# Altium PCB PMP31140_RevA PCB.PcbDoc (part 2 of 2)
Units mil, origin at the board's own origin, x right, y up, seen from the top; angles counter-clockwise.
Board outline 6181.25 x 1625 mil, 2 copper layers (Top Layer, Bottom Layer), stack 62 mil thick; 98 components, 49 nets, 210 pads, 6 vias.
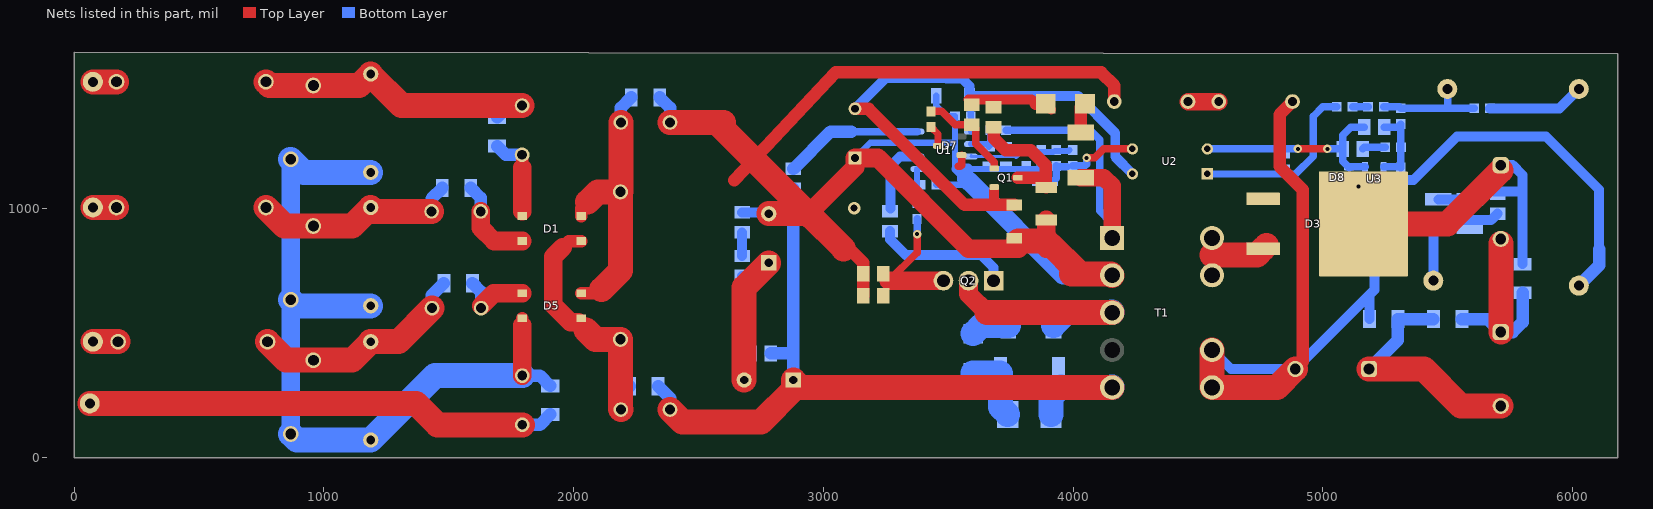
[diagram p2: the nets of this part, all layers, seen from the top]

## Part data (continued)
R34: library part CMP-0022325-3, "RES, 30.9 k, 1%, 0.1 W, 0603", Manufacturer=Vishay-Dale, Power_W=100mW, Supplier Part Number 1=541-30.9KHCT-ND, TempCo="100 ppm/C", Tolerance_%=1%, Value2=0.1W, Value_Code=30k9, ValueDisplayed=30.9k
R36: "RES, 100 k, 1%, 0.125 W, 0805", Manufacturer=Vishay-Dale, Power_W=0.125, Supplier Part Number 1=541-100KCCT-ND, TempCo="100 ppm/C", Tolerance_%=1, Value1=1%, Value2=0.125W, Value_Code=100k
R37: library part CRCW060322K1FKEA, "RES, 22.1 k, 1%, 0.1 W, 0603", Manufacturer=Vishay-Dale, Power_W=0.1, Supplier Part Number 1=541-22.1KHCT-ND, TempCo="100 ppm/C", Tolerance_%=1, Value1=1%, Value2=0.1W, Value_Code=22k1, ValueDisplayed=22.1k
RF1 RF2 RF3: library part CMP-0014490-1, "RES, 1.0, 5%, 1 W, TH, 2-Leads, Axial, Dia 3.8mm, Pin Spaing 15.2mm", Manufacturer="TT Electronics/IRC", Power_W=1W, Supplier Part Number 1=989-1255-1-ND, TempCo="300 ppm/C", Tolerance_%=5%, Value_Code=1R00, ValueDisplayed=1.0
RV1 RV2 RV3: library part CMP-0001853-2, "SIOV Metal Oxide Leaded Varistor, 300VAC, 3500A, TH", Manufacturer=TDK, Supplier Part Number 1=495-1434-ND
T1: library part CMP-0094613-1, "TRANSFORMER", Frequency_Fixed=65kHz, Manufacturer=Wurth, Operating Temperature Range="-40°C to +125°C", Voltage_Isolation_Vrms=4kV
TP1 TP2 TP4 TP6: library part CMP-0055137-1, "Test Point, Miniature, Red, TH", Color=Red, Manufacturer=Keystone, Supplier Part Number 1=36-5000-ND
TP3 TP7: "Test Point, Miniature, Red, TH", Color=Red, Manufacturer=Keystone, Supplier Part Number 1=36-5000-ND
TP5 TP8: "Test Point, Miniature, Black, TH", Color=Black, Manufacturer=Keystone, Supplier Part Number 1=36-5001-ND
U1: "Constant-Voltage, Constant-Current Flyback Controller Using Opto-Coupler Feedback, D0007A", Alternate Manufacturer="Texas Instruments", Alternate PartNumber=UCC28740D
U2: "Optocoupler, 5 kV, 80-160% CTR, TH", Manufacturer="Fairchild Semiconductor", Supplier Part Number 1=FOD817A-ND, Voltage_Isolation_Vrms=5000V
U3: library part CMP-0084731-1, "High Bandwidth Low-Iq Programmable Shunt Regulator, DBZ0003A (SOT-23-3)", Alternate Manufacturer="Texas Instruments"

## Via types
v1: diameter 34, hole 16, Top Layer to Bottom Layer, 5 vias
v2: diameter 50, hole 28, Top Layer to Bottom Layer, 1 vias

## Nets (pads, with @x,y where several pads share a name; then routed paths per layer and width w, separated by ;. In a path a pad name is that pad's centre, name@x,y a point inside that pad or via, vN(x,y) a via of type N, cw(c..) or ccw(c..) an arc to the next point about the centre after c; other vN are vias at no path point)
GND: C7.2 C8.2 C10.2 C11.2 C24.2 C26.1 R14.1 R34.1 T1.6 T1.7 TP5.1 TP8.1 U3.3 | length 5265.7
  Top Layer w50: C26.1@4878.48,1427.1 4826.52,1375.14 4826.52,1167.23 4918.75,1075 4918.75,385.14 C11.2@4889.86,356.25
  Top Layer w100: T1.7@4556.25,432.24 T1.6@4556.25,282.63 4816.25,282.63 C11.2@4889.86,356.25
  Bottom Layer w40: T1.7@4556.25,432.24 4632.24,356.25 C11.2@4889.86,356.25 5181,647.39 ; C24.2@5121.25,906.25 5193.75,906.25 ; R14.1@5186.56,556.25 5186.56,641.83 5181,647.39 ; 5206.25,1048.07 5206.25,921.39 5206.25,672.64 5181,647.39 ; U3.3@5206.25,1071.51 5284.25,1071.51 R34.1@5312.5,1099.75 5325.25,1112.5 5362.5,1112.5 5537.5,1287.5 5893.85,1287.5 6106.25,1075.1 6106.25,836.49 ; TP5.1@5442.31,710.05 C7.2@5442.31,921.66 ; C7.2@5446.85,937.32 5462.5,952.97 5674.22,952.97 C10.2@5700,978.75
  Bottom Layer w50: 5193.75,906.25 cw(c5209.16,906.25) 5206.25,921.39 cw(c5209.16,906.25) 5209.16,921.66 5442.31,921.66 C7.2@5462.5,921.66 ; TP8.1@6025,690.13 6106.25,771.38 6106.25,836.49
NetC1_1: C1.1 L1.1 R2.1 RF1.1 RV1.2 | length 1224.1
  Top Layer w100: RF1.1@767.96,1506.25 782.82,1491.39 RV1.2@957.78,1491.39 1141.44,1491.39 C1.1@1185.95,1535.9 ; C1.1@1187.5,1537.45 C1.1@1185.95,1535.9 ; L1.1@1793.75,1410.93 1310.93,1410.93 C1.1@1185.95,1535.9
  Bottom Layer w50: R2.1@1693.75,1363.34 1741.34,1410.93 L1.1@1793.75,1410.93
NetC1_2: C1.2 C5.2 C12.2 D5.2 L6.2 R17.2 RV1.1 RV2.1 RV3.1 | length 3175.5
  Top Layer w50: 1793.75,531.89 1794.39,532.53 D5.2@1794.39,559.4
  Top Layer w75: 1793.75,531.89 1793.75,330.31 L6.2@1794.39,329.68
  Bottom Layer w50: L6.2@1794.39,329.68 1864.91,329.68 R17.2@1906.25,288.34
  Bottom Layer w75: RV3.1@867.22,96.11 RV2.1@867.22,633.61 RV1.1@867.22,1196.11
  Bottom Layer w100: RV3.1@867.22,96.11 891.44,71.9 C12.2@1187.5,71.9 1445.28,329.68 L6.2@1794.39,329.68 ; RV2.1@867.22,633.61 891.44,609.4 C5.2@1187.5,609.4 ; RV1.1@867.22,1196.11 919.59,1143.75 C1.2@1187.5,1143.75
NetC2_1: C2.1 D2.2 L2.2 R1.2 R3.2 R4.2 R7.2 T1.5 | length 3200.1
  Top Layer w100: L2.2@2385.93,193.75 2435.93,143.75 2750,143.75 2879.68,273.43 C2.1@2879.68,312.5 2909.54,282.63 T1.5@4156.25,282.63
  Bottom Layer w50: R3.2@2338.34,287.5 2385.93,239.91 L2.2@2385.93,193.75 ; R1.2@2790,418.75 2879.68,418.75 ; C2.1@2879.68,312.5 2879.68,418.75 ; R7.2@2879.68,1077.59 2879.68,418.75
  Bottom Layer w100: D2.2@3912.01,175 3912.01,245.87 3950.99,284.85 3953.2,282.63 T1.5@4156.25,282.63 ccw(c4154.04,282.63) T1.5@4154.04,284.85
NetC2_2: C2.2 C6.1 R5.1 R6.2 | length 767
  Top Layer w100: C2.2@2682.82,312.5 2682.82,682.82 C6.1@2781.25,781.25
  Bottom Layer w40: R5.1@2675,621.25 R6.2@2675,728.75 2766.25,728.75 2781.25,743.75 C6.1@2781.25,781.25
NetC3_1: C3.1 D1.1 D5.1 L2.1 R3.1 | length 1047.4
  Top Layer w50: 1956.25,843.75 1981.25,868.75 D1.1@2030.61,868.75 ; 2030.61,531.89 2050,512.5
  Top Layer w75: 1956.25,843.75 1918.75,806.25 1918.75,612.5 1987.5,543.75 2018.75,543.75 2030.61,531.89
  Top Layer w100: 2050,512.5 2087.5,475 C3.1@2187.5,475 2187.5,195.32 L2.1@2189.07,193.75
  Bottom Layer w50: L2.1@2189.07,193.75 2189.07,252.41 R3.1@2224.16,287.5
NetC3_2: C3.2 D1.4 D5.4 L4.1 R10.1 | length 1120.9
  Top Layer w50: D5.4@2030.61,659.4 2096.9,659.4 2112.5,675 ; D1.4@2030.61,968.75 2030.61,999.36 2056.25,1025
  Top Layer w100: 2056.25,1025 2096.8,1065.55 C3.2@2187.5,1065.55 ; 2112.5,675 2187.5,750 C3.2@2187.5,1065.55 ; L4.1@2189.07,1343.75 2189.07,1067.13 C3.2@2187.5,1065.55
  Bottom Layer w50: L4.1@2189.07,1343.75 2189.07,1402.41 R10.1@2230.41,1443.75
NetC4_2: C4.2 C9.1 R8.1 R13.2 | length 754.3
  Top Layer w100: C9.1@5712.5,503.89 C4.2@5712.5,859.19
  Bottom Layer w50: R13.2@5557.09,556.25 5660.14,556.25 C9.1@5712.5,503.89 5760.14,503.89 5800,543.75 R8.1@5800,661.66
NetC5_1: C5.1 L3.1 R9.1 RF2.1 RV2.2 | length 842.8
  Top Layer w100: RF2.1@767.96,1003.1 842.18,928.89 RV2.2@957.78,928.89 1113.29,928.89 C5.1@1187.5,1003.1 1203.1,987.5 L3.1@1431.25,987.5
  Bottom Layer w50: L3.1@1431.25,987.5 1431.25,1038.34 R9.1@1474.16,1081.25
NetC9_2: C9.2 C11.1 R13.1 R14.2 | length 978.6
  Top Layer w100: C11.1@5185.14,356.25 5404.77,356.25 5552.41,208.61 C9.2@5712.5,208.61
  Bottom Layer w50: C11.1@5185.14,356.25 5300.74,471.85 R14.2@5300.74,556.25 R13.1@5442.91,556.25
NetC12_1: C12.1 L5.1 R15.1 RF3.1 RV3.2 | length 895.5
  Top Layer w100: RF3.1@774.21,465.6 848.43,391.39 RV3.2@957.78,391.39 1113.29,391.39 C12.1@1187.5,465.6 1298.43,465.6 L5.1@1432.82,600
  Bottom Layer w50: L5.1@1432.82,600 1432.82,652.41 R15.1@1480.41,700
NetC13_1: C13.1 Q1.3 R18.1 | length 508.5
  Top Layer w50: R18.1@3681.64,1324.55 3681.64,1280.86 3731.25,1231.25 3831.25,1231.25 3890.01,1172.49 C13.1@3890.01,1097.3 ; Q1.3@3778.49,1121.95 3853.88,1121.95 cw(c3853.88,1083.15) C13.1@3890.01,1097.3 ; C13.1@3892.68,1083.15 ccw(c3853.88,1083.15) C13.1@3890.01,1097.3
NetC14_1: C14.1 C15.2 C16.1 C17.1 Q1.2 U1.1 U2.4 | length 2399.8
  Top Layer w40: 3684.01,1013.42 3684.01,1071.52
  Top Layer w50: C15.2@3126.74,1398.31 3180.83,1398.31 3565.72,1013.42 3684.01,1013.42 C14.1@3764.38,1013.42
  Bottom Layer w25: C17.1@3585.68,1450 3590.46,1445.22 C16.1@3590.46,1369.34 3591.25,1368.56 U1.1@3591.25,1306.84
  Bottom Layer w40: C15.2@3126.74,1398.31 3249.92,1521.5 3490.04,1521.5 3492.24,1519.29 3555.71,1519.29 3585.68,1489.32 C17.1@3585.68,1450 4019.34,1450 4168.75,1300.59 4168.75,1206.25 U2.4@4237.5,1137.5
NetC18_1: C18.1 R20.1 R27.1 U1.2 | length 222.2
  Bottom Layer w25: U1.2@3591.25,1256.84 R27.1@3668.5,1256.84 ; R27.1@3662.5,1246.21 3668.5,1252.22 R27.1@3668.5,1256.84 ; R20.1@3662.5,1306.5 R20.1@3668.5,1312.5 R27.1@3668.5,1256.84 ; C18.1@3731.5,1245.62 3720.27,1256.84 R27.1@3668.5,1256.84
NetC19_1: C19.1 R26.1 U1.5 | length 137.3
  Bottom Layer w25: R26.1@3375,1020.22 3375,1155.16 U1.5@3376.68,1156.84
NetC20_1: C20.1 R25.1 R29.1 R34.2 U3.2 | length 316
  Bottom Layer w30: U3.2@5243.65,1165.99 5309.25,1165.99 R34.2@5312.5,1162.75 5312.5,1243.75 5312.5,1325 R25.1@5312.5,1337.25 5300.25,1325 C20.1@5246.25,1325
NetC20_2: C20.2 C21.1 D8.1 R32.1 U2.2 U3.1 | length 848.6
  Top Layer w30: v1(4900,1237.5) v1(5017.76,1237.5)
  Bottom Layer w30: U2.2@4537.5,1237.5 v1(4900,1237.5) ; v1(5017.76,1237.5) C21.1@5079,1237.5 ; C20.2@5166.25,1325 5111.19,1325 5079,1292.8 C21.1@5079,1237.5 ; U3.1@5168.85,1165.99 5108.54,1165.99 D8.1@5104.94,1162.4 5079,1188.35 C21.1@5079,1237.5
NetC21_2: C21.2 R29.2 | length 93.3
  Bottom Layer w30: C21.2@5159,1237.5 5165.25,1243.75 R29.2@5249.75,1243.75
NetC22_1: C22.1 R33.2 R35.1 U2.3 | length 392.7
  Top Layer w30: v1(4053.91,1201.46) 4087.41,1201.46 4123.45,1237.5 U2.3@4237.5,1237.5
  Bottom Layer w30: R35.1@3918.75,1107.56 R35.1@3919,1107.32 3931.99,1120.31 R33.2@3931.99,1166.06 ; R33.2@3931.99,1169.59 R33.2@3931.99,1166.06 ; 3975,1166.06 R33.2@3931.99,1166.06 ; C22.1@3998.28,1169.97 4047.14,1169.97 4053.91,1176.74 v1(4053.91,1201.46)
NetC22_2: C22.2 C23.1 R33.1 R37.2 U1.3 | length 398.8
  Bottom Layer w10: U1.3@3591.25,1206.84 U1.3@3591.25,1211.57
  Bottom Layer w12: U1.3@3591.25,1206.84 3629.03,1206.84 3630.35,1208.16 3769.74,1208.16 3771.05,1206.84
  Bottom Layer w20: 3771.05,1206.84 3789.46,1225.25 R37.2@3806.25,1225.25
  Bottom Layer w25: R37.2@3806.25,1225.25 3852.01,1225.25 R33.1@3918.75,1225.25 ; R33.1@3928.94,1229.24 3981.38,1229.24 C22.2@3985.19,1233.04
NetC24_1: C24.1 D8.3 R36.2 | length 228
  Bottom Layer w30: D8.3@5010.45,1125 5028.75,1106.71 R36.2@5028.75,1006.25 5028.75,918.75 C24.1@5018.75,908.75
NetC25_1: C25.1 C26.2 | length 123.1
  Top Layer w70: C25.1@4460.14,1427.1 C26.2@4583.2,1427.1
NetD1_2: D1.2 L3.2 R9.2 | length 364.1
  Top Layer w75: L3.2@1628.1,987.5 1628.1,921.9 1681.25,868.75 D1.2@1794.39,868.75
  Bottom Layer w50: R9.2@1588.34,1081.25 1628.1,1041.49 L3.2@1628.1,987.5
NetD1_3: D1.3 L1.2 R2.2 | length 341.1
  Top Layer w50: 1793.75,1162.5 L1.2@1793.75,1214.07
  Top Layer w75: 1793.75,987.5 1793.75,1162.5
  Bottom Layer w50: R2.2@1693.75,1249.16 1728.84,1214.07 L1.2@1793.75,1214.07
NetD2_1: D2.1 D4.1 R4.1 | length 284.5
  Bottom Layer w100: D4.1@3600,340.01 3706.35,340.01 R4.1@3708.86,337.5 3708.86,204.13 D2.1@3737.99,175
NetD3_1: D3.1 D3.3 T1.9 T1.10 | length 234.9
  Top Layer w100: 4556.25,812.5 4735.93,812.5 D3.3@4760.93,837.5 D3.3@4775,851.57
NetD4_2: D4.2 R12.2 | length 154.7
  Bottom Layer w100: D4.2@3600,497.49 3633.76,531.25 R12.2@3740.7,531.25
NetD5_3: D5.3 L5.2 R15.2 | length 300
  Top Layer w75: L5.2@1629.68,609.4 1679.68,659.4 D5.3@1794.39,659.4
  Bottom Layer w50: R15.2@1594.59,700 1629.68,664.91 L5.2@1629.68,600
NetD6_1: D6.1 R18.2 R19.2 | length 347.8
  Top Layer w40: R19.2@3581.25,1436.26 3643.75,1436.26 3832.49,1436.26 3850,1418.75 ; D6.1@3890.01,1418.75 D6.1@3912.5,1396.26
  Top Layer w50: 3850,1418.75 D6.1@3890.01,1418.75
NetD6_2: D6.2 R16.2 | length 125
  Top Layer w50: R16.2@4031.25,1303.05 4031.25,1402.51 cw(c4047.49,1402.51) D6.2@4047.49,1418.75
NetD7_3: D7.3 R21.1 | length 86.5
  Top Layer w30: R21.1@3431.25,1325 3459.01,1297.24 D7.3@3459.01,1250
NetL6_1: L6.1 R17.1 TP6.1 | length 1896.5
  Top Layer w100: TP6.1@62.5,218.75 1368.75,218.75 1454.68,132.82 L6.1@1794.39,132.82
  Bottom Layer w50: L6.1@1794.39,132.82 1864.91,132.82 R17.1@1906.25,174.16
NetQ1_1: Q1.1 R19.1 R21.2 | length 386.2
  Top Layer w30: R21.2@3431.25,1387.99 3474.75,1387.99 3527.75,1335 R19.1@3593.75,1335 3609.35,1319.4 3609.35,1258.8 3684.01,1184.15 Q1.1@3684.01,1170.66
NetQ2_1: Q2.1 R24.2 | length 547.8
  Bottom Layer w40: R24.2@3266.96,908.72 3266.96,875.66 3329.01,813.61 3329.01,812.5 3631.25,812.5 3681.25,762.5 3681.25,710.14 Q2.1@3681.64,709.75
NetQ2_2: Q2.2 R12.1 T1.3 | length 919.4
  Top Layer w75: Q2.2@3581.25,709.75 3581.25,656.25 3655.65,581.85
  Top Layer w100: 3655.65,581.85 T1.3@4156.25,581.85
  Bottom Layer w100: R12.1@3921.8,531.25 3972.4,581.85 T1.3@4156.25,581.85 ccw(c4153.25,581.85) T1.3@4153.25,584.85
NetQ2_3: Q2.3 R26.2 R30.2 R31.2 | length 514.4
  Top Layer w30: R31.2@3262.55,709.75 3375,822.2 v1(3375,896.1) v1@3375,898.1
  Top Layer w75: R31.2@3262.55,709.75 Q2.3@3480.86,709.75
  Bottom Layer w30: v1(3375,896.1) R26.2@3375,957.23
NetR1_1: R1.1 R5.2 | length 137
  Bottom Layer w40: R5.2@2675,541.25 2675,453.75 R1.1@2710,418.75
NetR6_1: R6.1 R11.2 | length 95
  Bottom Layer w40: R6.1@2675,808.75 R11.2@2675,903.75
NetR7_1: R7.1 U1.8 | length 559.3
  Bottom Layer w30: 3112.5,1306.25 3376.09,1306.25 U1.8@3376.68,1306.84
  Bottom Layer w50: R7.1@2879.68,1157.59 3028.93,1306.84 3111.91,1306.84 3112.5,1306.25
NetR16_1: R16.1 R20.2 T1.1 | length 1152.9
  Top Layer w70: R16.1@4031.25,1121.95 4123.45,1121.95 4156.25,1089.15 T1.1@4156.25,881.06
  Bottom Layer w30: R20.2@3731.5,1312.5 4068.75,1312.5 4106.25,1275 4106.25,989.56 4151.06,944.75 4153.25,944.75 4156.25,941.75 T1.1@4156.25,881.06
NetR22_1: R22.1 R28.2 | length 62
  Bottom Layer w30: R28.2@5119,1406.25 R22.1@5181,1406.25
NetR22_2: R22.2 R23.2 R25.2 TP7.1 | length 442.6
  Bottom Layer w30: R22.2@5244,1406.25 5306.5,1406.25 R25.2@5312.5,1400.25 5499.75,1400.25 ; TP7.1@5498.47,1477.67 5499.75,1476.39 5499.75,1400.25 ; R23.2@5606,1400 5605.76,1400.25 5499.75,1400.25
NetR24_1: R24.1 U1.6 | length 292.8
  Bottom Layer w40: R24.1@3268.75,999.69 3268.75,1168.75 3306.84,1206.84 U1.6@3376.68,1206.84
NetR28_1: R28.1 R32.2 U2.1 | length 724.4
  Bottom Layer w30: U2.1@4537.5,1137.5 4849.9,1135.99 4889.86,1135.8 4962.5,1208.43 4962.5,1368.75 5000,1406.25 R28.1@5056,1406.25
NetRF1_2: RF1.2 TP1.1 | length 94.5
  Top Layer w100: TP1.1@75,1506.25 RF1.2@169.54,1506.25
NetRF2_2: RF2.2 TP2.1 | length 94.5
  Top Layer w100: TP2.1@75,1003.1 RF2.2@169.54,1003.1
NetRF3_2: RF3.2 TP4.1 | length 100.8
  Top Layer w100: TP4.1@75,465.6 RF3.2@175.79,465.6
PGND: C6.2 C13.2 C14.2 C15.1 C16.2 C17.2 C18.2 C19.2 C23.2 C25.2 D7.1 L4.2 R10.2 R11.1 R27.2 R30.1 R31.1 R35.2 R37.1 T1.2 U1.4 | length 7142
  Top Layer w30: 3540.02,1167.47 3548.48,1167.47 3553.49,1172.49 D7.1@3553.49,1212.6
  Top Layer w50: 2643.75,1112.5 2645.25,1114.1 3048.68,1543.75 4112.5,1543.75 4164.86,1491.39 C25.2@4164.86,1427.1 ; 3081.25,837.5 3103.75,837.5 3160,781.25 R31.1@3160,737.5 R30.1@3160,650
  Top Layer w75: 2940.65,978.1 3126.74,1164.19 C15.1@3126.74,1201.46 3217.29,1201.46 3581.25,837.5 3781.25,837.5 ; 3892.68,837.5 C13.2@3892.68,953.23
  Top Layer w100: L4.2@2385.93,1343.75 2600,1343.75 ; 2581.25,1335 2938.15,978.1 ; C6.2@2781.25,978.1 2938.15,978.1 ; 2946.9,969.35 2938.15,978.1 ; 3081.25,837.5 2940.65,978.1 2938.15,978.1 ; C14.2@3781.25,868.07 3892.68,868.07 ; 3912.5,851.57 4013.57,750.51 ; 3993.75,736.43 4151.27,736.43 T1.2@4156.25,731.45
  Bottom Layer w25: C15.1@3126.74,1201.46 3187.78,1262.5 3471.27,1262.5 ; C17.2@3451.82,1450 3451.82,1410.68 3493.16,1369.34 C16.2@3527.47,1369.34 3527.47,1262.5 ; C19.2@3452.01,1094.34 3570.51,1094.34 3583.49,1107.32 ; 3475,1262.5 3527.47,1262.5 ; 3533.96,1156.84 3527.47,1163.34 3527.47,1262.5 ; 3540.02,1167.47 3580.62,1167.47 U1.4@3591.25,1156.84 C23.2@3859.39,1156.84 ; R35.2@3852.01,1111.31 R35.2@3856,1107.32 3856,1153.46 C23.2@3859.39,1156.84 ; C23.2@3872.51,1169.97 C23.2@3859.39,1156.84
  Bottom Layer w40: R11.1@2675,983.75 2775.6,983.75 C6.2@2781.25,978.1 ; 3533.96,1156.84 3573.21,1117.59
  Bottom Layer w50: R10.2@2344.59,1443.75 2385.93,1402.41 L4.2@2385.93,1343.75
  Bottom Layer w75: 3573.21,1117.59 3583.49,1107.32 3959.35,731.45 T1.2@4156.25,731.45
  other v2: 3123.01,1000
Vout: C4.1 C7.1 C8.1 C10.1 D3.2 D8.2 R8.2 R23.1 R36.1 TP3.1 | length 1948.7
  Top Layer w100: D3.2@5162.5,937.5 5498.47,937.5 C4.1@5712.5,1151.53
  Bottom Layer w30: D8.2@5104.94,1087.6 v1(5143.75,1087.6)
  Bottom Layer w40: D8.2@5104.94,1087.6 5104.94,1010.06 R36.1@5108.75,1006.25 ; C7.1@5462.5,1035.84 C8.1@5587.5,1035.84 ; 5587.5,1067.14 5795.64,1067.14 5800,1071.51 ; R23.1@5669,1400 5947.33,1400 TP3.1@6025,1477.67 ; C4.1@5712.5,1172.49 5760.14,1172.49 5800,1132.63 5800,1071.51 ; R8.2@5800,775.84 5800,1071.51
pads on no net: D7.2 T1.4

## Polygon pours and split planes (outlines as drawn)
PGND on Top Layer "PGND_L01_P024" (solid, remove dead copper, pour order 24): 3184.99,543.75 cw(c3116.24,543.75) 3116.24,475 2559.99,475 cw(c2559.99,518.75) 2516.24,518.75 2516.24,1537.5 cw(c2572.49,1537.5) 2572.49,1593.75 4140.72,1593.75 cw(c4140.72,1549.48) 4184.99,1549.48 4184.99,702.11 cw(c4162.35,702.11) 4162.35,679.47 3976.78,679.47 cw(c3976.78,768.75) 3887.5,768.75 ccw(c3856.25,768.75) 3856.25,800 3203.74,800 ccw(c3203.74,781.25) 3184.99,781.25
NetQ2_3 on Top Layer "NETQ2_3_L01_P023" (solid, pour order 23): 3212.5,768.75 cw(c3225,768.75) 3225,781.25 3350,781.25 cw(c3350,768.75) 3362.5,768.75 3362.5,637.5 cw(c3337.5,637.5) 3337.5,612.5 3231.25,612.5 cw(c3231.25,631.25) 3212.5,631.25
GND on Top Layer "GND_L01_P019" (solid, pour order 19): 4505.83,462.5 cw(c4605.83,462.5) 4605.83,562.5 5812.5,562.5 ccw(c5812.5,587.5) 5837.5,587.5 5837.5,818.75 cw(c5912.5,818.75) 5912.5,893.75 6109.45,893.75 cw(c6109.45,837.5) 6165.7,837.5 6165.7,52.56 cw(c6131.89,52.56) 6131.89,18.75 4562.08,18.75 cw(c4562.08,75) 4505.83,75
NetD3_1 on Top Layer "NETD3_1_L01_P018" (solid, pour order 18): 4500,868.07 cw(c4563.44,868.07) 4563.44,931.5 4627.76,931.5 ccw(c4627.76,972.5) 4668.75,972.5 4668.75,1011.57 cw(c4735.93,1011.57) 4735.93,1078.75 4800,1078.75 cw(c4800,1041.25) 4837.5,1041.25 4837.5,683.75 cw(c4806.25,683.75) 4806.25,652.5 4551.25,652.5 cw(c4551.25,703.75) 4500,703.75
Vout on Top Layer "VOUT_L01_P017" (solid, pour order 17): 5456.25,637.5 ccw(c5456.25,737.5) 5556.25,737.5 5556.25,850 cw(c5650,850) 5650,943.75 6128.2,943.75 ccw(c6128.2,981.25) 6165.7,981.25 6165.7,1559.3 ccw(c6131.25,1559.3) 6131.25,1593.75 5037.5,1593.75 ccw(c5037.5,1531.25) 4975,1531.25 4975,718.75 ccw(c5056.25,718.75) 5056.25,637.5
NetD6_1 on Top Layer "NETD6_1_L01_P004" (solid, remove dead copper, pour order 4): 3950,1290.67 3772.35,1290.67 cw(c3771.8,1306.22) 3756.25,1306.22 3756.25,1471.91 cw(c3775,1471.91) 3775,1490.66 3937.5,1490.66 cw(c3937.5,1478.17) 3950,1478.16
PGND on Bottom Layer "PGND_L02_P026" (solid, remove dead copper, pour order 26): 4177.36,681.25 ccw(c4177.36,710.14) 4206.25,710.14 4206.25,750 ccw(c4175,750) 4175,781.25 4117.47,781.25 cw(c4117.47,825) 4073.72,825 4073.72,1569.14 ccw(c4047.14,1569.14) 4047.14,1595.73 2564.48,1595.73 ccw(c2564.48,1537.5) 2506.25,1537.5 2506.25,550 ccw(c2543.75,550) 2543.75,512.5 3193.75,512.5 ccw(c3193.75,550) 3231.25,550 3231.25,808.04 cw(c3266.96,808.04) 3266.96,843.75 3759.32,843.75 cw(c3759.32,813.61) 3789.46,813.61 3789.46,781.25 ccw(c3889.46,781.25) 3889.46,681.25 3975.4,681.25
GND on Bottom Layer "GND_L02_P022" (solid, pour order 22): 4553.95,18.75 cw(c4553.95,66.45) 4506.25,66.45 4506.25,518.75 cw(c4543.75,518.75) 4543.75,556.25 4875,556.25 ccw(c4875,606.25) 4925,606.25 4925,1562.5 cw(c4962.5,1562.5) 4962.5,1600 6137.5,1600 cw(c6137.5,1568.75) 6168.75,1568.75 6168.75,56.25 cw(c6131.25,56.25) 6131.25,18.75
Vout on Bottom Layer "VOUT_L02_P020" (solid, pour order 20): 5393.75,1062.5 cw(c5418.75,1062.5) 5418.75,1087.5 5640.93,1087.5 ccw(c5640.93,1106.71) 5660.14,1106.71 5660.14,1194.35 cw(c5674.22,1194.35) 5674.22,1208.43 5822.81,1208.43 cw(c5822.81,1193.75) 5837.5,1193.75 5837.5,756.25 cw(c5831.25,756.25) 5831.25,750 5778.89,750 cw(c5778.89,768.75) 5760.14,768.75 5760.14,1002.36 ccw(c5743.75,1002.36) 5743.75,1018.75 5410.84,1018.75 cw(c5410.84,1035.84) 5393.75,1035.84
NetC2_1 on Bottom Layer "NETC2_1_L02_P012" (solid, remove dead copper, pour order 12): 3976.2,398.8 cw(c3976.2,387.5) 3987.5,387.5 ccw(c4034.99,387.5) 4034.99,340.01 4037.5,340.01 cw(c4037.5,283.76) 4093.75,283.76 4093.75,75 cw(c4068.75,75) 4068.75,50 3896.31,50 cw(c3896.31,83.81) 3862.5,83.81 3862.5,386.3 cw(c3875,386.3) 3875,398.8
NetD4_2 on Bottom Layer "NETD4_2_L02_P010" (solid, remove dead copper, pour order 10): 3768.75,450 ccw(c3768.75,468.75) 3787.5,468.75 3787.5,581.25 ccw(c3768.75,581.25) 3768.75,600 3543.75,600 ccw(c3543.75,581.25) 3525,581.25 3525,458.96 ccw(c3533.96,458.96) 3533.96,450
NetD2_1 on Bottom Layer "NETD2_1_L02_P008" (solid, remove dead copper, pour order 8): 3475,400 ccw(c3475,381.25) 3456.25,381.25 3456.25,87.5 ccw(c3493.75,87.5) 3493.75,50 3756.25,50 ccw(c3756.25,81.25) 3787.5,81.25 3787.5,368.75 ccw(c3756.25,368.75) 3756.25,400

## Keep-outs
Keep-Out Layer:
  lines w10: -5,0 ccw(c0,0) 0,-5 cw(c0,0) -5,0 ; -5,3450 cw(c0,3450) 0,3455 ccw(c0,3450) -5,3450 ; 4950,3455 cw(c4950,3450) 4955,3450 ccw(c4950,3450) 4950,3455 ; 6024.86,15.42 ccw(c6024.86,20.42) 6029.86,20.42 cw(c6024.86,20.42) 6024.86,15.42
  text ".Layer_Name" at 577,-858.49 h60

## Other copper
Top Layer:
  text ".Layer_Name" at 577,-858.49 h60
Bottom Layer:
  text ".Layer_Name" at 577,-858.49 h60

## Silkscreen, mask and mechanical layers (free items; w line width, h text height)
Top Overlay:
  text "PMP31140_RevA" at 22.5,663.75 h60
  text ".Layer_Name" at 577,-858.49 h30
Bottom Overlay:
  text ".Layer_Name" at 577,-858.49 h30
Top Paste:
  text ".Layer_Name" at 577,-858.49 h60
Bottom Paste:
  text ".Layer_Name" at 577,-858.49 h60
Top Solder:
  text ".Layer_Name" at 577,-858.49 h60
  text ".Layer_Name" at 577,-858.49 h60
Bottom Solder:
  text ".Layer_Name" at 577,-858.49 h60
Drill Guide:
  text ".Layer_Name" at 577,-858.49 h60
M1 Board Outline:
  lines w10: 6181.25,1617.36 6181.25,0 0,0 0,1625 6181.25,1618.75
  text ".Layer_Name" at 577,-858.49 h60
M2 Board Dimensions:
  rectangle: 0,-275 125,-150
  rectangle: 125,-400 500,-275
  lines w7: 0,-275 1000,-275 ; 125,-400 125,-150 ; 250,-400 250,-150 ; 500,-400 500,-150 ; 750,-400 750,-150 ; 0,-400 1000,-400 1000,-150 0,-150 0,-400
  text ".Layer_Name" at 577,-858.49 h60
M3 3D STEP Top:
  text ".Layer_Name" at 577,-858.49 h60
M4 3D STEP Bottom:
  text ".Layer_Name" at 577,-858.49 h60
M5 Assembly Top:
  lines w10: -292,-930.17 6308,-930.17 ; -292,-726.83 6310,-726.83 ; -292,-523.5 -292,-1133.5 3713,-1133.5 6310,-1133.5 6310,-523.5 -291.5,-523.5 -291.5,-1133.5 1284,-1133.5 ; 2173,-1133.5 2173,-523.5 ; 3440,-726.83 3440,-523.5 ; 4280,-726.83 4280,-523.5 ; 4902,-1140 4902,-937.17
  text "PCB VIEWED FROM TOP SIDE" at -228.5,-655.67 h60
  text "BOARD #:" at 2248,-655.67 h60
  text ".PRJ_Number" at 2793.5,-655.67 h60
  text "REV:" at 3638,-655.67 h60
  text ".PCB_Rev" at 3929.5,-655.67 h60
  text "SVN REV:" at 4476,-655.67 h60
  text ".VersionControl_RevNumber" at 4982,-655.67 h60
  text "TID #:" at 2248,-859 h60
  text ".TID" at 2793.5,-859 h60
  text "PLOT NAME =" at -228.5,-1064.34 h60
  text ".plot_File_Name" at 577,-1064.34 h60
  text "GENERATED    :" at 2250,-1064.34 h60
  text ".Print_Date" at 3119.5,-1064.34 h60
  text ".Print_Time" at 3848.5,-1064.34 h60
  text "TEXAS INSTRUMENTS" at 5113,-1064.34 h60
M6 Assembly Bottom:
  lines w10: -292.5,-727.33 6309.5,-727.33 ; -290.5,-930.67 6309.5,-930.67 ; 1115.5,-1140.5 1115.5,-937.67 ; 1737.5,-727.33 1737.5,-524 ; 2577.5,-727.33 2577.5,-524 ; 3844.5,-1134 3844.5,-524 ; 4733.5,-1134 6309,-1134 6309,-524 -292.5,-524 -292.5,-1134 2304.5,-1134 6309.5,-1134 6309.5,-524
  text ".VersionControl_RevNumber" at 1035.5,-656.17 h60
  text "SVN REV:" at 1541.5,-656.17 h60
  text ".PCB_Rev" at 2088,-656.17 h60
  text "REV:" at 2379.5,-656.17 h60
  text ".PRJ_Number" at 3224,-656.17 h60
  text "BOARD #:" at 3769.5,-656.17 h60
  text "PCB VIEWED FROM BOTTOM SIDE" at 6246,-656.17 h60
  text ".TID" at 3224,-859.5 h60
  text "TID #:" at 3769.5,-859.5 h60
  text "TEXAS INSTRUMENTS" at 904.5,-1064.84 h60
  text ".Print_Time" at 2169,-1064.84 h60
  text ".Print_Date" at 2898,-1064.84 h60
  text "GENERATED    :" at 3767.5,-1064.84 h60
  text ".plot_File_Name" at 5440.5,-1064.84 h60
  text "PLOT NAME =" at 6246,-1064.84 h60
M8 LPKF Text Bottom:
  text "PMP31140_RevA" at 131.25,1262.5 h60
M9 Title Sheet:
  drawing of 57 lines, arcs and shapes, not listed
  text "1" at 739.84,8036.5 h70
  text "2" at 3235.5,8036.5 h70
  text "3" at 5724.84,8036.5 h70
  text "4" at 8231.51,8036.5 h70
  text "5" at 10730.5,8036.5 h70
  text "6" at 13235.5,8036.5 h70
  text "A" at -416.5,6893.5 h70
  text "A" at 14383.5,6893.5 h70
  text "B" at -416.5,4513.5 h70
  text "B" at 14383.5,4513.5 h70
  text "C" at -416.5,2138.5 h70
  text "C" at 14383.5,2138.5 h70
  text "PROJECT TITLE:" at 11343.5,277.5 h45
  text ".PRJ_Title" at 11393.5,144.17 h70
  text "DESIGNED FOR:" at 11343.5,-23.5 h45
  text ".PRJ_Customer" at 11393.5,-163.5 h70
  text "D" at -416.5,-231.5 h70
  text "D" at 14383.5,-231.5 h70
  text "FILE NAME:" at 11343.5,-323.5 h45
  text ".PCB_File_Name_No_Path" at 11393.5,-443.5 h70
  text "Texas Instruments (TI) and/or its licensors do not warrant the accuracy or completeness of this specification" at 6374,-605.34 h45
  text "ENGINEER:" at 11343.5,-613.5 h45
  text "LAYOUT BY:" at 12848.5,-613.5 h45
  text "or any information contained therein. TI and/or its licensors do not warrant that this design will meet" at 6329.01,-718 h45
  text ".PRJ_Engineer" at 11393.5,-768.49 h70
  text ".PCB_Layout" at 12899,-768.49 h70
  text "the specifications, will be suitable for your application or fit for any particular purpose, or will operate in" at 6329.01,-830.67 h45
  text ".Layer_Name" at 577,-858.49 h60
  text "ALTIUM DESIGNER VERSION:" at 12848.5,-923.5 h45
  text "an implementation. TI and/or its licensors do not warrant that the design is production worthy. You should" at 6329.01,-943.33 h45
  text "completely validate and test your design implementation to confirm the system functionality for your application." at 6374,-1056 h45
  text ".print_Scale" at 11393.5,-1056.83 h70
  text ".Application_BuildNumber" at 12899,-1056.83 h70
  text "1" at 739.84,-1263.5 h70
  text "2" at 3235.5,-1263.5 h70
  text "3" at 5724.84,-1263.5 h70
  text "4" at 8231.51,-1263.5 h70
  text "5" at 10730.5,-1263.5 h70
  text "6" at 13235.5,-1263.5 h70
M10 Fab Notes:
  text ".Layer_Name" at 577,-858.49 h60
M11 Gerber Information:
  lines w10: -292,-930.17 6308,-930.17 ; -292,-726.83 6310,-726.83 ; -292,-523.5 -292,-1133.5 3713,-1133.5 6310,-1133.5 6310,-523.5 -291.5,-523.5 -291.5,-1133.5 1284,-1133.5 ; 2173,-1133.5 2173,-523.5 ; 3440,-726.83 3440,-523.5 ; 4280,-726.83 4280,-523.5 ; 4902,-1140 4902,-937.17
  text "ALL ARTWORK VIEWED FROM TOP SIDE" at -228.5,-655.67 h60
  text "BOARD #:" at 2248,-655.67 h60
  text ".PRJ_Number" at 2793.5,-655.67 h60
  text "REV:" at 3638,-655.67 h60
  text ".PCB_Rev" at 3929.5,-655.67 h60
  text "SVN REV:" at 4476,-655.67 h60
  text ".VersionControl_RevNumber" at 4982,-655.67 h60
  text "LAYER NAME =" at -228.5,-858.49 h60
  text "TID #:" at 2248,-859 h60
  text ".TID" at 2793.5,-859 h60
  text "PLOT NAME =" at -228.5,-1064.34 h60
  text ".plot_File_Name" at 577,-1064.34 h60
  text "GENERATED    :" at 2250,-1064.34 h60
  text ".Print_Date" at 3119.5,-1064.34 h60
  text ".Print_Time" at 3848.5,-1064.34 h60
  text "TEXAS INSTRUMENTS" at 5113,-1064.34 h60
M12 Stackup:
  text ".Layer_Name" at 577,-858.49 h60
M13 Component Bodies Top:
  text ".Layer_Name" at 577,-858.49 h60
M14 Component Bodies Bottom:
  text ".Layer_Name" at 577,-858.49 h60
M15 Courtyards Top:
  text ".Layer_Name" at 577,-858.49 h60
M16 Courtyards Bottom:
  text ".Layer_Name" at 577,-858.49 h60
Drill Drawing:
  text ".Layer_Name" at 577,-858.49 h60

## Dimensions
0,0 to 6181.25,0 on M2 Board Dimensions
0,-400 to 1000,-400 on M2 Board Dimensions
0,0 to 6181.25,1617.36 on M2 Board Dimensions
